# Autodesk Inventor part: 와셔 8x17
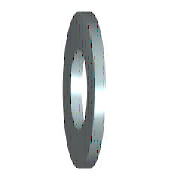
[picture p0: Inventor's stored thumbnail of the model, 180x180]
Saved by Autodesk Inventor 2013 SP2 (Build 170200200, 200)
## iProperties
Created: 2012-02
Part Number: 와셔 8x17
Material: 강철, 연강
Description: 평면 와셔
Document SubType Name: Modeling
Standard: KS B 1326
Designer: mduedu
Standards Organization: KS
Language: ko-KR
Size Designation: 8x17
Categories: <MemberInstance><Categories><Category DisplayName="조임쇠" InternalName="e4da775c-781d-43d5-af7c-5136215cf5a6" Mnemonic="FSTN"><Category DisplayName="와셔" InternalN
Density: 1 g/cm^3
IsCustomPart: 1
Author: mduedu
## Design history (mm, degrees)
sketch "스케치"
  geometry: C1 r 8.5 at (0, 0); C2 r 4.5 at (0, 0); 1 further point
  constraints: 2 centre point, 2 coincident
  dimensions: "d0" = 9 diameter of C2 (= SD1); "d1" = 17 diameter of C1 (= SD2)
extrude "본체" new body sketch "스케치" distance "d2" = 1.6 (= SD); taper "d3" = 0 deg
workaxis "Work Axis1"
workplane "Work Plane1"
body "Solid1"
other parameters: "SD1" = 9 [user parameter; used in 1 equation term], "SD2" = 17 [user parameter; used in 1 equation term], "SD" = 1.6 [user parameter; used in 1 equation term], "d4" = 0, "d5" = 0, "d6" = 0, "d7" = 0, "NND" = 8 [user parameter]
